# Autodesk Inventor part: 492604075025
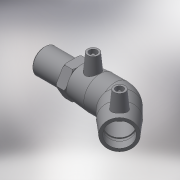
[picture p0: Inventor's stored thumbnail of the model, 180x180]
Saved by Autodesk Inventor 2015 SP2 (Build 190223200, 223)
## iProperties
Created: 2017-06
Part Number: 492604075025
Material: Generic
Description: PLASSON 45° ELBOW TRANSITION MALE 75-2.1/2"
Document SubType Name: Modeling
Designer: KIM
Mass: 843.056 g
Surface Area: 1263.15 cm^2
Volume: 843.056 cm^3
Density: 1 g/cm^3
Appearance: Default
Author: KIM
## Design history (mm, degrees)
derived "492604.ipt"
feature "Solid1::492604.ipt"
tag "TaggingFeature1"
body "Solid1"
other parameters: "d2" = 98, "d4" = 45, "d5" = 88.2, "d8" = 168 deg, "d10" = 28.4, "d11" = 9.46667, "d29" = 62, "d30" = 15, "d31" = 63, "d34" = 5 deg, "d41" = 4, "d42" = 14, "d43" = 0, "d49" = 75, "d50" = 48.75, "d51" = 28.4, "d52" = 73.13, "d54" = 135 deg, "d86" = 44.1, "d87" = 135 deg, "d90" = 71, "d91" = 0, "d92" = 71, "d93" = 0, "d101" = 3, "d102" = 0, "d107" = 0.1, "d108" = 59, "d109" = 75.184, "d110" = 46, "d111" = 11.5, "d112" = 98, "d113" = 52.6288, "d114" = 41.4, "d116" = 2.94, "d122" = 0, "d123" = 3.7592, "d_" = 75, "L_" = 226, "L_1" = 71, "D_" = 59, "A_" = 62, "d_2" = 12, "L_2" = 46, "R_" = 75.184, "D_1" = 98
